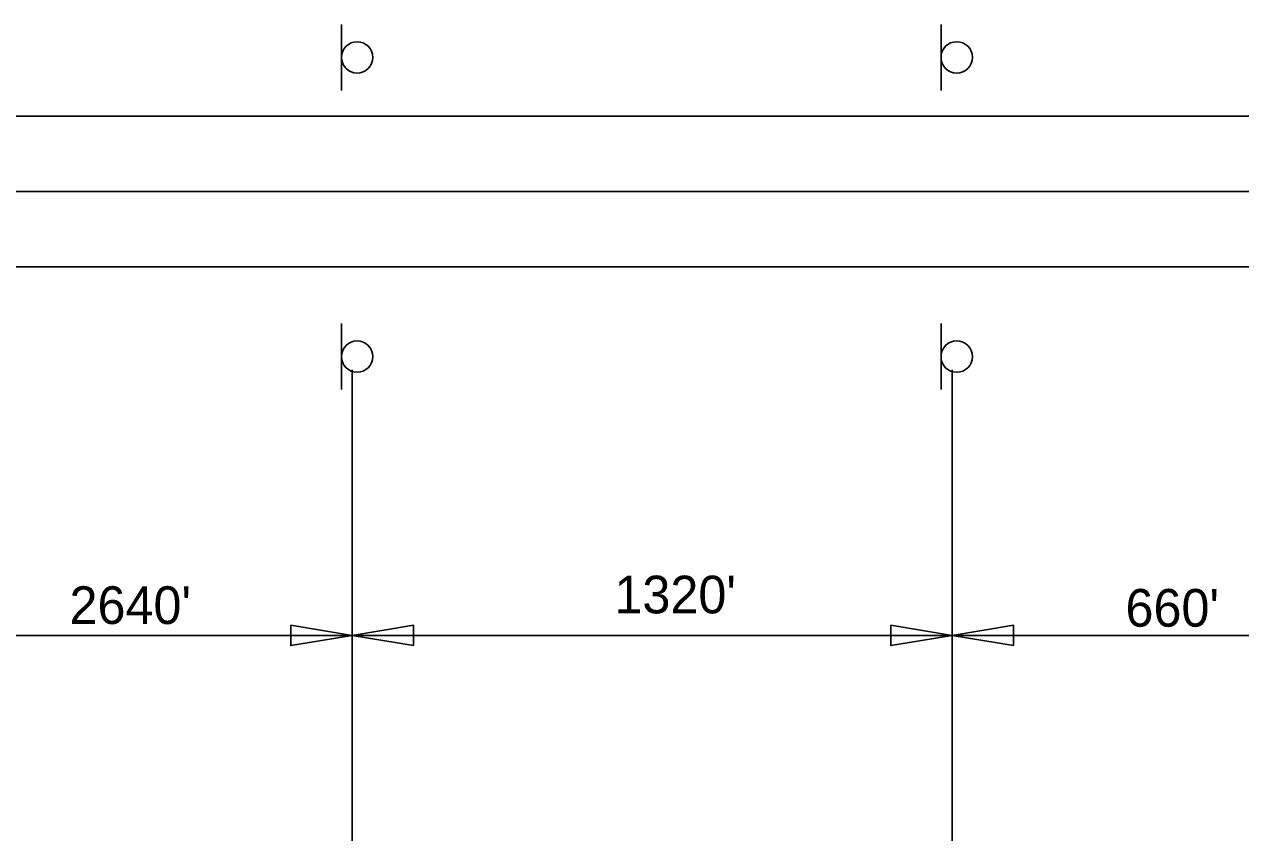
# Model space of a CAD drawing. Extents: x 2155255 to 2162649, y 140388 to 141878.
# Drawn here: x 2156578.8 to 2156772.7, y 140827.8 to 140956.6 of the extents above; entities that cross this region are included whole.
import ezdxf

# ---------------------------------------------------------------- set-up
doc = ezdxf.new("R2010")
doc.units = 0
for name, color, linetype in [('Default', 7, 'Continuous'), ('PR_Dimensions1', 7, 'Continuous'), ('PR_Traffic_Control_Devices_Temp', 7, 'Continuous'), ('PR_Traffic_Temp_Txt', 7, 'Continuous'), ('TOPO_Asphalt', 7, 'Continuous')]:
    doc.layers.add(name, color=color, linetype=linetype)

# ---------------------------------------------------------------- blocks, each defined once
blk = doc.blocks.new('TCSIGN')
at = {"layer": 'Default'}
blk.add_line((5.26, 2.5), (-5.26, 2.5), dxfattribs=at)
blk.add_circle((0, 0), 2.5, dxfattribs=at)
blk = doc.blocks.new('Arrowhd')
at = {"layer": 'Default'}
blk.add_lwpolyline([(0.3175, -0.0529), (0.3175, 0.0529), (0, 0)], close=True, dxfattribs=at)

msp = doc.modelspace()

# ---------------------------------------------------------------- linework, layer by layer
at = {"layer": 'PR_Dimensions1'}
for p, q in [((2156631.06, 140901.56), (2156631.06, 140791.06)), ((2156726.71, 140901.56), (2156726.71, 140812.83)), ((2156561.46, 140859.25), (2156631.06, 140859.25)), ((2156631.06, 140859.25), (2156726.71, 140859.25)), ((2156805.54, 140859.25), (2156726.71, 140859.25))]:
    msp.add_line(p, q, dxfattribs=at)
at = {"layer": 'TOPO_Asphalt'}
for p, q in [((2157147.83, 140941.97), (2156447.24, 140941.97)), ((2157147.76, 140929.97), (2156447.37, 140929.97)), ((2157147.69, 140917.97), (2156447.51, 140917.97)), ((2157147.69, 140917.97), (2156447.51, 140917.97))]:
    msp.add_line(p, q, dxfattribs=at)

# ---------------------------------------------------------------- block references
at = {"layer": 'PR_Dimensions1', "xscale": 30.761459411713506, "yscale": 30.761459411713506, "rotation": 180}
for p in [(2156631.06, 140859.25), (2156726.71, 140859.25)]:
    msp.add_blockref('Arrowhd', p, dxfattribs=at)
at = {"layer": 'PR_Dimensions1', "xscale": 30.761459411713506, "yscale": 30.761459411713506}
for p in [(2156631.06, 140859.25), (2156726.71, 140859.25)]:
    msp.add_blockref('Arrowhd', p, dxfattribs=at)
at = {"layer": 'PR_Traffic_Control_Devices_Temp', "rotation": 89.99999999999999}
for p in [(2156631.87, 140951.31), (2156727.43, 140951.31), (2156631.87, 140903.66), (2156727.43, 140903.66)]:
    msp.add_blockref('TCSIGN', p, dxfattribs=at)

# ---------------------------------------------------------------- texts
at = {"layer": 'PR_Traffic_Temp_Txt'}
for s, p in [("1320'", (2156672.87, 140862.76)), ("2640'", (2156586.02, 140861.07)), ("660'", (2156754.33, 140860.64))]:
    msp.add_text(s, height=6, rotation=360, dxfattribs=at).set_placement(p)

doc.saveas('drawing.dxf')
